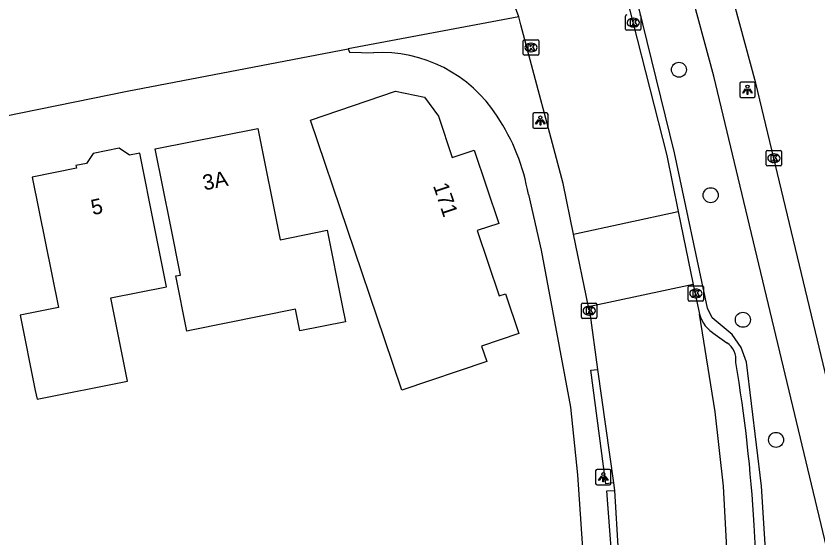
# Model space of a CAD drawing. Extents: x 162990 to 165007, y 383433 to 384336.
# Drawn here: x 164223.8 to 164276, y 384166.2 to 384200.1 of the extents above; entities that cross this region are included whole.
import ezdxf

# ---------------------------------------------------------------- set-up
doc = ezdxf.new("R2010")
doc.units = 0
for name, color, linetype in [('IMGEO_Boom', 7, 'Continuous'), ('IMGEO_Kolk', 7, 'Continuous'), ('IMGEO_Lichtpunt', 7, 'Continuous'), ('IMGEO_Pand', 7, 'Continuous'), ('IMGEO_Pand_nummerreeks', 7, 'Continuous'), ('IMGEO_Rijbaan_lokaal_open', 7, 'Continuous'), ('IMGEO_Voetpad_open', 7, 'Continuous')]:
    doc.layers.add(name, color=color, linetype=linetype)

msp = doc.modelspace()

# ---------------------------------------------------------------- linework, layer by layer
at = {"layer": 'IMGEO_Boom'}
for centre in [(164266.908, 384196.642), (164268.975, 384188.477), (164271.07, 384180.372), (164273.231, 384172.56)]:
    msp.add_circle(centre, 0.489, dxfattribs=at)
at = {"layer": 'IMGEO_Kolk'}
for p, q in [((164263.437, 384199.281), (164263.437, 384200.133)), ((164263.925, 384199.987), (164263.95, 384199.987)), ((164264.438, 384200.133), (164264.438, 384199.281)), ((164264.364, 384199.207), (164263.512, 384199.207)), ((164263.948, 384199.427), (164263.923, 384199.427)), ((164256.78, 384197.661), (164256.78, 384198.513)), ((164256.855, 384198.587), (164257.707, 384198.587)), ((164257.268, 384198.367), (164257.293, 384198.367)), ((164257.781, 384198.513), (164257.781, 384197.661)), ((164257.707, 384197.587), (164256.855, 384197.587)), ((164257.291, 384197.807), (164257.266, 384197.807)), ((164272.589, 384190.459), (164272.589, 384191.311)), ((164272.664, 384191.385), (164273.516, 384191.385)), ((164273.59, 384191.311), (164273.59, 384190.459)), ((164273.077, 384191.165), (164273.102, 384191.165)), ((164273.516, 384190.385), (164272.664, 384190.385)), ((164273.1, 384190.605), (164273.075, 384190.605)), ((164267.509, 384181.662), (164267.509, 384182.514)), ((164267.584, 384182.588), (164268.436, 384182.588)), ((164268.51, 384182.514), (164268.51, 384181.662)), ((164267.997, 384182.368), (164268.022, 384182.368)), ((164260.643, 384181.462), (164261.495, 384181.462)), ((164268.436, 384181.588), (164267.584, 384181.588)), ((164268.02, 384181.808), (164267.995, 384181.808)), ((164260.568, 384180.536), (164260.568, 384181.388)), ((164261.056, 384181.242), (164261.081, 384181.242)), ((164261.569, 384181.388), (164261.569, 384180.536)), ((164261.495, 384180.462), (164260.643, 384180.462)), ((164261.079, 384180.682), (164261.054, 384180.682))]:
    msp.add_line(p, q, dxfattribs=at)
for points in [[(164263.437, 384199.281), (164263.437, 384200.133)], [(164263.758, 384199.907), (164263.881, 384199.907), (164263.881, 384199.756), (164264.011, 384199.907), (164264.175, 384199.907), (164264.029, 384199.756), (164264.182, 384199.507), (164264.03, 384199.507), (164263.945, 384199.671), (164263.881, 384199.604), (164263.881, 384199.507), (164263.758, 384199.507), (164263.758, 384199.907)], [(164264.438, 384200.133), (164264.438, 384199.281)], [(164264.364, 384199.207), (164263.512, 384199.207)], [(164256.78, 384197.661), (164256.78, 384198.513)], [(164256.855, 384198.587), (164257.707, 384198.587)], [(164257.101, 384198.287), (164257.224, 384198.287), (164257.224, 384198.136), (164257.354, 384198.287), (164257.518, 384198.287), (164257.372, 384198.136), (164257.525, 384197.887), (164257.373, 384197.887), (164257.288, 384198.051), (164257.224, 384197.984), (164257.224, 384197.887), (164257.101, 384197.887), (164257.101, 384198.287)], [(164257.781, 384198.513), (164257.781, 384197.661)], [(164257.707, 384197.587), (164256.855, 384197.587)], [(164272.589, 384190.459), (164272.589, 384191.311)], [(164272.664, 384191.385), (164273.516, 384191.385)], [(164273.59, 384191.311), (164273.59, 384190.459)], [(164272.91, 384191.085), (164273.033, 384191.085), (164273.033, 384190.934), (164273.163, 384191.085), (164273.327, 384191.085), (164273.181, 384190.934), (164273.334, 384190.685), (164273.182, 384190.685), (164273.097, 384190.849), (164273.033, 384190.782), (164273.033, 384190.685), (164272.91, 384190.685), (164272.91, 384191.085)], [(164273.516, 384190.385), (164272.664, 384190.385)], [(164267.509, 384181.662), (164267.509, 384182.514)], [(164267.584, 384182.588), (164268.436, 384182.588)], [(164268.51, 384182.514), (164268.51, 384181.662)], [(164267.83, 384182.288), (164267.953, 384182.288), (164267.953, 384182.137), (164268.083, 384182.288), (164268.247, 384182.288), (164268.101, 384182.137), (164268.254, 384181.888), (164268.102, 384181.888), (164268.017, 384182.052), (164267.953, 384181.985), (164267.953, 384181.888), (164267.83, 384181.888), (164267.83, 384182.288)], [(164260.643, 384181.462), (164261.495, 384181.462)], [(164268.436, 384181.588), (164267.584, 384181.588)], [(164260.568, 384180.536), (164260.568, 384181.388)], [(164260.889, 384181.162), (164261.012, 384181.162), (164261.012, 384181.011), (164261.142, 384181.162), (164261.306, 384181.162), (164261.16, 384181.011), (164261.313, 384180.762), (164261.161, 384180.762), (164261.076, 384180.926), (164261.012, 384180.859), (164261.012, 384180.762), (164260.889, 384180.762), (164260.889, 384181.162)], [(164261.569, 384181.388), (164261.569, 384180.536)], [(164261.495, 384180.462), (164260.643, 384180.462)]]:
    msp.add_lwpolyline(points, dxfattribs=at)
for centre, start, end in [((164263.514, 384200.131), 91.552, 178.448), ((164263.514, 384200.131), 91.552, 178.448), ((164264.362, 384200.131), 1.552, 88.448), ((164264.362, 384200.131), 1.552, 88.448), ((164263.514, 384199.283), 181.552, 268.448), ((164263.514, 384199.283), 181.552, 268.448), ((164264.362, 384199.283), 271.552, 358.448), ((164264.362, 384199.283), 271.552, 358.448), ((164256.857, 384198.511), 91.552, 178.448), ((164256.857, 384198.511), 91.552, 178.448), ((164257.705, 384198.511), 1.552, 88.448), ((164257.705, 384198.511), 1.552, 88.448), ((164256.857, 384197.663), 181.552, 268.448), ((164256.857, 384197.663), 181.552, 268.448), ((164257.705, 384197.663), 271.552, 358.448), ((164257.705, 384197.663), 271.552, 358.448), ((164272.666, 384191.309), 91.552, 178.448), ((164272.666, 384191.309), 91.552, 178.448), ((164273.514, 384191.309), 1.552, 88.448), ((164273.514, 384191.309), 1.552, 88.448), ((164272.666, 384190.461), 181.552, 268.448), ((164272.666, 384190.461), 181.552, 268.448), ((164273.514, 384190.461), 271.552, 358.448), ((164273.514, 384190.461), 271.552, 358.448), ((164267.586, 384182.512), 91.552, 178.448), ((164267.586, 384182.512), 91.552, 178.448), ((164268.434, 384182.512), 1.552, 88.448), ((164268.434, 384182.512), 1.552, 88.448), ((164260.645, 384181.386), 91.552, 178.448), ((164260.645, 384181.386), 91.552, 178.448), ((164261.493, 384181.386), 1.552, 88.448), ((164261.493, 384181.386), 1.552, 88.448), ((164267.586, 384181.664), 181.552, 268.448), ((164267.586, 384181.664), 181.552, 268.448), ((164268.434, 384181.664), 271.552, 358.448), ((164268.434, 384181.664), 271.552, 358.448), ((164260.645, 384180.538), 181.552, 268.448), ((164260.645, 384180.538), 181.552, 268.448), ((164261.493, 384180.538), 271.552, 358.448), ((164261.493, 384180.538), 271.552, 358.448)]:
    msp.add_arc(centre, 0.0765, start, end, dxfattribs=at)
for centre, major_axis, ratio, start_param, end_param in [((164263.924, 384199.707), (-0.387, 0.002), 0.722429, 4.712389, 7.853982), ((164263.949, 384199.707), (-0.39, 0.002), 0.717154, 1.570796, 4.712389), ((164257.267, 384198.087), (-0.387, 0.002), 0.722429, 4.712389, 7.853982), ((164257.292, 384198.087), (-0.39, 0.002), 0.717154, 1.570796, 4.712389), ((164273.076, 384190.885), (-0.387, 0.002), 0.722429, 4.712389, 7.853982), ((164273.101, 384190.885), (-0.39, 0.002), 0.717154, 1.570796, 4.712389), ((164267.996, 384182.088), (-0.387, 0.002), 0.722429, 4.712389, 7.853982), ((164268.021, 384182.088), (-0.39, 0.002), 0.717154, 1.570796, 4.712389), ((164261.055, 384180.962), (-0.387, 0.002), 0.722429, 4.712389, 7.853982), ((164261.08, 384180.962), (-0.39, 0.002), 0.717154, 1.570796, 4.712389)]:
    msp.add_ellipse(centre, major_axis=major_axis, ratio=ratio, start_param=start_param, end_param=end_param, dxfattribs=at)
at = {"layer": 'IMGEO_Lichtpunt'}
for p, q in [((164270.874, 384195.744), (164270.874, 384194.937)), ((164270.874, 384195.744), (164270.874, 384194.937)), ((164271.776, 384195.839), (164270.968, 384195.839)), ((164271.776, 384195.839), (164270.968, 384195.839)), ((164271.87, 384194.937), (164271.87, 384195.744)), ((164271.87, 384194.937), (164271.87, 384195.744)), ((164270.968, 384194.843), (164271.776, 384194.843)), ((164270.968, 384194.843), (164271.776, 384194.843)), ((164257.392, 384193.735), (164257.392, 384192.928)), ((164257.392, 384193.735), (164257.392, 384192.928)), ((164258.294, 384193.83), (164257.486, 384193.83)), ((164258.294, 384193.83), (164257.486, 384193.83)), ((164258.388, 384192.928), (164258.388, 384193.735)), ((164258.388, 384192.928), (164258.388, 384193.735)), ((164257.486, 384192.834), (164258.294, 384192.834)), ((164257.486, 384192.834), (164258.294, 384192.834)), ((164261.484, 384170.536), (164261.484, 384169.729)), ((164261.484, 384170.536), (164261.484, 384169.729)), ((164262.386, 384170.631), (164261.578, 384170.631)), ((164262.386, 384170.631), (164261.578, 384170.631)), ((164262.48, 384169.729), (164262.48, 384170.536)), ((164262.48, 384169.729), (164262.48, 384170.536)), ((164261.578, 384169.635), (164262.386, 384169.635)), ((164261.578, 384169.635), (164262.386, 384169.635))]:
    msp.add_line(p, q, dxfattribs=at)
for points in [[(164271.248, 384195.408), (164271.287, 384195.38), (164271.099, 384195.118), (164271.061, 384195.145), (164271.248, 384195.408)], [(164271.35, 384195.36), (164271.397, 384195.36), (164271.397, 384195.038), (164271.35, 384195.038), (164271.35, 384195.36)], [(164271.46, 384195.38), (164271.498, 384195.407), (164271.685, 384195.145), (164271.646, 384195.117), (164271.46, 384195.38)], [(164257.766, 384193.399), (164257.805, 384193.371), (164257.617, 384193.109), (164257.579, 384193.136), (164257.766, 384193.399)], [(164257.978, 384193.371), (164258.016, 384193.398), (164258.203, 384193.136), (164258.164, 384193.108), (164257.978, 384193.371)], [(164257.868, 384193.351), (164257.915, 384193.351), (164257.915, 384193.029), (164257.868, 384193.029), (164257.868, 384193.351)], [(164261.858, 384170.2), (164261.897, 384170.172), (164261.709, 384169.91), (164261.671, 384169.937), (164261.858, 384170.2)], [(164261.96, 384170.152), (164262.007, 384170.152), (164262.007, 384169.83), (164261.96, 384169.83), (164261.96, 384170.152)], [(164262.07, 384170.172), (164262.108, 384170.199), (164262.295, 384169.937), (164262.256, 384169.909), (164262.07, 384170.172)]]:
    msp.add_lwpolyline(points, dxfattribs=at)
for centre in [(164271.373, 384195.542), (164257.891, 384193.533), (164261.983, 384170.334)]:
    msp.add_circle(centre, 0.0994, dxfattribs=at)
for centre, start, end in [((164270.968, 384195.744), 90, 180), ((164270.968, 384195.744), 90, 180), ((164271.776, 384195.744), 0, 90), ((164271.776, 384195.744), 0, 90), ((164270.968, 384194.937), 180, 270), ((164270.968, 384194.937), 180, 270), ((164271.776, 384194.937), 270, 0), ((164271.776, 384194.937), 270, 360), ((164257.486, 384193.735), 90, 180), ((164257.486, 384193.735), 90, 180), ((164258.294, 384193.735), 0, 90), ((164258.294, 384193.735), 0, 90), ((164257.486, 384192.928), 180, 270), ((164257.486, 384192.928), 180, 270), ((164258.294, 384192.928), 270, 0), ((164258.294, 384192.928), 270, 360), ((164261.578, 384170.536), 90, 180), ((164261.578, 384170.536), 90, 180), ((164262.386, 384170.536), 0, 90), ((164262.386, 384170.536), 0, 90), ((164261.578, 384169.729), 180, 270), ((164261.578, 384169.729), 180, 270), ((164262.386, 384169.729), 270, 0), ((164262.386, 384169.729), 270, 360)]:
    msp.add_arc(centre, 0.0946, start, end, dxfattribs=at)
at = {"layer": 'IMGEO_Pand'}
for points in [[(164242.936, 384193.362), (164248.47, 384195.239), (164250.348, 384194.859), (164251.253, 384193.613), (164252.151, 384190.939), (164253.575, 384191.417), (164255.178, 384186.645), (164253.782, 384186.176), (164255.208, 384181.929), (164255.616, 384182.066), (164256.485, 384179.479), (164254.068, 384178.667), (164254.409, 384177.653), (164248.867, 384175.792), (164247.743, 384179.123), (164242.936, 384193.362)], [(164232.825, 384191.488), (164239.498, 384192.826), (164240.949, 384185.583), (164244.013, 384186.197), (164244.996, 384181.295), (164245.205, 384180.25), (164242.227, 384179.653), (164241.946, 384181.058), (164235.185, 384179.703), (164234.884, 384179.643), (164234.167, 384183.225), (164234.468, 384183.285), (164233.812, 384186.56), (164232.825, 384191.488)], [(164232.803, 384186.307), (164231.821, 384191.209), (164231.154, 384191.076), (164230.469, 384191.532), (164228.78, 384191.193), (164228.347, 384190.543), (164227.655, 384190.405), (164227.69, 384190.231), (164224.814, 384189.655), (164226.515, 384181.164), (164224.034, 384180.667), (164225.016, 384175.765), (164225.129, 384175.202), (164231.021, 384176.382), (164229.936, 384181.798), (164233.561, 384182.524), (164232.803, 384186.307)]]:
    msp.add_lwpolyline(points, dxfattribs=at)
at = {"layer": 'IMGEO_Rijbaan_lokaal_open'}
for points in [[(164282.629, 384151.118), (164271.917, 384195.775), (164264.967, 384221.376)], [(164262.802, 384204.094), (164266.122, 384191.066), (164266.869, 384187.42)], [(164260.051, 384185.953), (164259.378, 384189.246), (164256.626, 384199.552), (164256.485, 384200.076)], [(164260.051, 384185.953), (164266.869, 384187.42)], [(164266.869, 384187.42), (164267.844, 384182.664)], [(164261.02, 384181.208), (164260.051, 384185.953)], [(164267.844, 384182.664), (164261.02, 384181.208)], [(164267.844, 384182.664), (164268.238, 384180.741)], [(164261.02, 384181.208), (164261.1, 384180.816), (164261.614, 384177.14)], [(164269.886, 384151.534), (164270.113, 384157.7), (164270.102, 384164.282), (164269.805, 384169.553), (164269.268, 384174.387), (164268.238, 384180.741)], [(164261.614, 384177.14), (164262.644, 384169.769)], [(164262.644, 384169.769), (164262.713, 384169.274)], [(164262.713, 384169.274), (164262.956, 384165.275)]]:
    msp.add_lwpolyline(points, dxfattribs=at)
msp.add_arc((164249.07, 384197.795), 7.757, 17.0981, 89.2724, dxfattribs=at)
at = {"layer": 'IMGEO_Voetpad_open'}
for points in [[(164279.829, 384151.74), (164269.173, 384196.228), (164265.331, 384210.398)], [(164271.962, 384148.128), (164272.034, 384148.712), (164272.414, 384151.199), (164272.677, 384163.35), (164272.274, 384169.542), (164271.311, 384177.619), (164270.949, 384178.573), (164270.369, 384179.413), (164269.071, 384180.496), (164268.767, 384181.12), (164266.623, 384191.243), (164263.373, 384204.511)], [(164256.485, 384200.076), (164245.375, 384198.004)], [(164035.172, 384154.601), (164077.591, 384163.416), (164136.425, 384175.642), (164181.684, 384185.212), (164230.991, 384195.25), (164245.375, 384198.004)], [(164245.375, 384198.004), (164245.464, 384197.793), (164247.023, 384197.746)], [(164257.107, 384188.517), (164257.94, 384184.892), (164259.844, 384174.681), (164260.314, 384170.278), (164260.746, 384163.915), (164260.697, 384154.993), (164260.321, 384149.044), (164259.897, 384145.876)], [(164269.267, 384179.424), (164270.019, 384178.881)], [(164262.644, 384169.769), (164262.155, 384169.707), (164261.184, 384177.086), (164261.614, 384177.14)], [(164262.956, 384165.275), (164262.512, 384165.244), (164262.216, 384169.24), (164262.713, 384169.274)]]:
    msp.add_lwpolyline(points, dxfattribs=at)
for centre, radius, start, end in [((164247.519, 384188.796), 8.964, 32.6136, 93.1735), ((164244.199, 384186.332), 13.092, 9.606, 33.8615), ((164270.39, 384181.362), 2.24, 196.0947, 239.9079), ((164269.283, 384177.767), 1.336, 352.8768, 56.5428), ((164178.157, 384161.858), 93.782, 3.15178, 9.66402), ((164141.245, 384158.742), 130.814, 358.15525, 3.62549)]:
    msp.add_arc(centre, radius, start, end, dxfattribs=at)

# ---------------------------------------------------------------- texts
at = {"layer": 'IMGEO_Pand_nummerreeks'}
for s, rotation, p in [('3A', 11.3388, (164236.018, 384188.783)), ('171', 288.5681, (164250.893, 384189.099)), ('5', 12.5046, (164228.758, 384187.171))]:
    msp.add_text(s, height=1, rotation=rotation, dxfattribs=at).set_placement(p)

doc.saveas('drawing.dxf')
